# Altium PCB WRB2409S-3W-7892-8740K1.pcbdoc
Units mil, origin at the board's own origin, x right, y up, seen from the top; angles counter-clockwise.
Board outline 933.1 x 582.7 mil, 2 copper layers (Top Layer, Bottom Layer), stack 30.8 mil thick; 27 components, 17 nets, 72 pads, 29 vias.
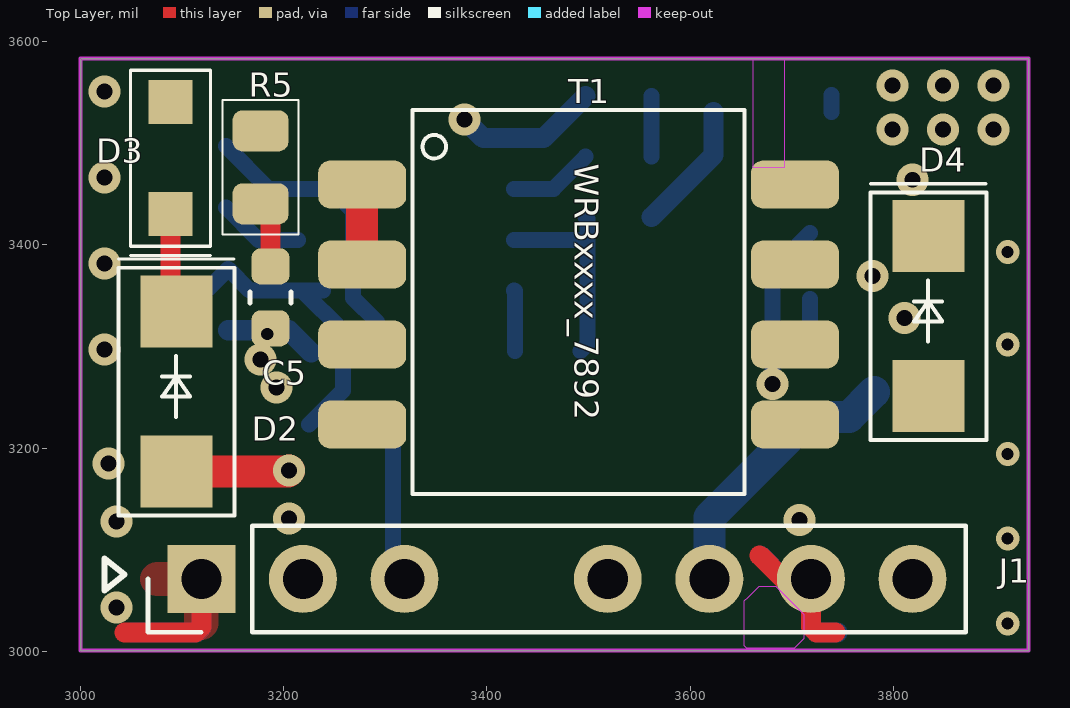
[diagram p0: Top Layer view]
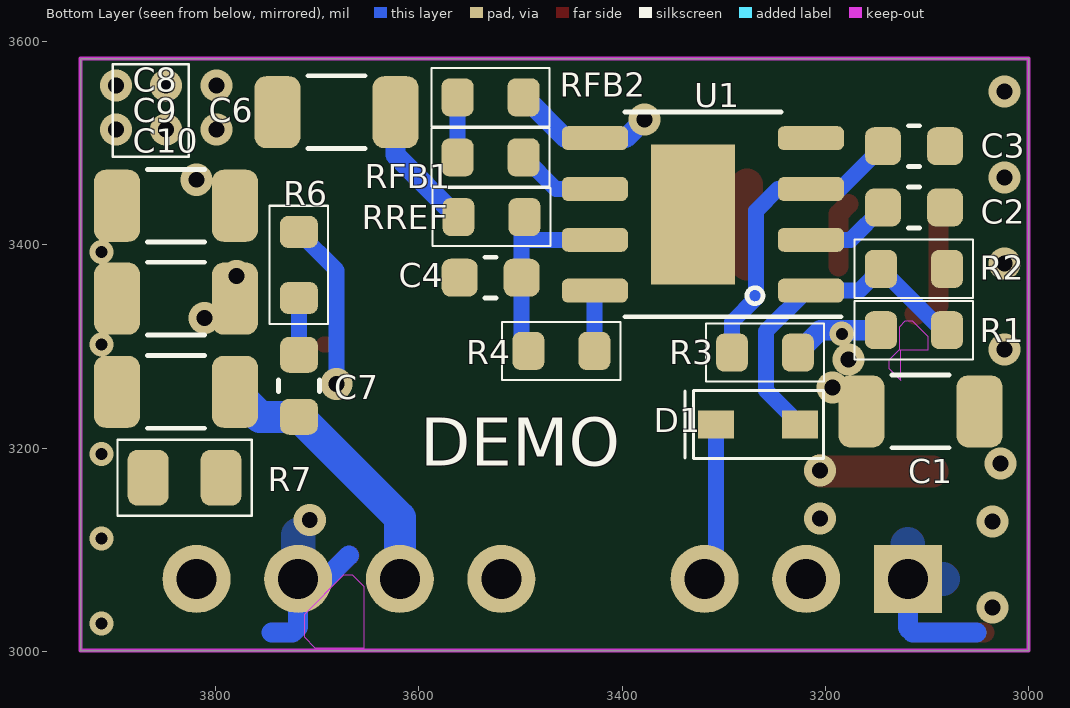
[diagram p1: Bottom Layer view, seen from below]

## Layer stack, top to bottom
Top Solder Mask Layer: solder mask 0.4, Dk 3.3
Top Layer: signal copper 1.4
Dielectric1: surface 28, FR4, Dk 4.5
Bottom Layer: signal copper 1.4
Bottom Solder Mask Layer: solder mask 0.4, Dk 3.3

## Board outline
3000,3583.5 3933.1,3583.5 3933.1,3000.8 3000,3000.8

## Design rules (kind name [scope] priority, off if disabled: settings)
BoardOutlineClearance safeClearance [All] p0: genericclearance=10 ignorepadtopadclearanceinfootprint=FALSE except(0: Arc-SplitContinuation Track-SplitContinuation SMDPad-SplitContinuation THPad-SplitContinuation Via-SplitContinuation Fill-SplitContinuation Poly-SplitContinuation Region-SplitContinuation Text-SplitContinuation)
BoardOutlineClearance Plane_innerPlane [All] p0: genericclearance=10 ignorepadtopadclearanceinfootprint=FALSE except(0: Arc-SplitContinuation Track-SplitContinuation SMDPad-SplitContinuation THPad-SplitContinuation Via-SplitContinuation Fill-SplitContinuation Poly-SplitContinuation Region-SplitContinuation Text-SplitContinuation)
BoardOutlineClearance Copper_CopperRegion [All] p0: genericclearance=10 ignorepadtopadclearanceinfootprint=FALSE except(0: Arc-SplitContinuation Track-SplitContinuation SMDPad-SplitContinuation THPad-SplitContinuation Via-SplitContinuation Fill-SplitContinuation Poly-SplitContinuation Region-SplitContinuation Text-SplitContinuation)
BoardOutlineClearance Copper_CopperRegion1 [All] p0: genericclearance=10 ignorepadtopadclearanceinfootprint=FALSE except(0: Arc-SplitContinuation Track-SplitContinuation SMDPad-SplitContinuation THPad-SplitContinuation Via-SplitContinuation Fill-SplitContinuation Poly-SplitContinuation Region-SplitContinuation Text-SplitContinuation)
BoardOutlineClearance Copper_CopperRegion2 [All] p0: genericclearance=10 ignorepadtopadclearanceinfootprint=FALSE except(0: Arc-SplitContinuation Track-SplitContinuation SMDPad-SplitContinuation THPad-SplitContinuation Via-SplitContinuation Fill-SplitContinuation Poly-SplitContinuation Region-SplitContinuation Text-SplitContinuation)
BoardOutlineClearance Copper_CopperRegion3 [All] p0: genericclearance=10 ignorepadtopadclearanceinfootprint=FALSE except(0: Arc-SplitContinuation Track-SplitContinuation SMDPad-SplitContinuation THPad-SplitContinuation Via-SplitContinuation Fill-SplitContinuation Poly-SplitContinuation Region-SplitContinuation Text-SplitContinuation)
BoardOutlineClearance Copper_CopperRegion4 [All] p0: genericclearance=10 ignorepadtopadclearanceinfootprint=FALSE except(0: Arc-SplitContinuation Track-SplitContinuation SMDPad-SplitContinuation THPad-SplitContinuation Via-SplitContinuation Fill-SplitContinuation Poly-SplitContinuation Region-SplitContinuation Text-SplitContinuation)
BoardOutlineClearance Copper_CopperRegion5 [All] p0: genericclearance=10 ignorepadtopadclearanceinfootprint=FALSE except(0: Arc-SplitContinuation Track-SplitContinuation SMDPad-SplitContinuation THPad-SplitContinuation Via-SplitContinuation Fill-SplitContinuation Poly-SplitContinuation Region-SplitContinuation Text-SplitContinuation)
BoardOutlineClearance Copper_CopperRegion6 [All] p0: genericclearance=10 ignorepadtopadclearanceinfootprint=FALSE except(0: Arc-SplitContinuation Track-SplitContinuation SMDPad-SplitContinuation THPad-SplitContinuation Via-SplitContinuation Fill-SplitContinuation Poly-SplitContinuation Region-SplitContinuation Text-SplitContinuation)
BoardOutlineClearance Copper_CopperRegion7 [All] p0: genericclearance=10 ignorepadtopadclearanceinfootprint=FALSE except(0: Arc-SplitContinuation Track-SplitContinuation SMDPad-SplitContinuation THPad-SplitContinuation Via-SplitContinuation Fill-SplitContinuation Poly-SplitContinuation Region-SplitContinuation Text-SplitContinuation)
BoardOutlineClearance Copper_CopperRegion8 [All] p0: genericclearance=10 ignorepadtopadclearanceinfootprint=FALSE except(0: Arc-SplitContinuation Track-SplitContinuation SMDPad-SplitContinuation THPad-SplitContinuation Via-SplitContinuation Fill-SplitContinuation Poly-SplitContinuation Region-SplitContinuation Text-SplitContinuation)
BoardOutlineClearance Copper_CopperRegion9 [All] p0: genericclearance=10 ignorepadtopadclearanceinfootprint=FALSE except(0: Arc-SplitContinuation Track-SplitContinuation SMDPad-SplitContinuation THPad-SplitContinuation Via-SplitContinuation Fill-SplitContinuation Poly-SplitContinuation Region-SplitContinuation Text-SplitContinuation)
BoardOutlineClearance Copper_CopperRegion10 [All] p0: genericclearance=10 ignorepadtopadclearanceinfootprint=FALSE except(0: Arc-SplitContinuation Track-SplitContinuation SMDPad-SplitContinuation THPad-SplitContinuation Via-SplitContinuation Fill-SplitContinuation Poly-SplitContinuation Region-SplitContinuation Text-SplitContinuation)
BoardOutlineClearance Copper_CopperRegion11 [All] p0: genericclearance=10 ignorepadtopadclearanceinfootprint=FALSE except(0: Arc-SplitContinuation Track-SplitContinuation SMDPad-SplitContinuation THPad-SplitContinuation Via-SplitContinuation Fill-SplitContinuation Poly-SplitContinuation Region-SplitContinuation Text-SplitContinuation)
BoardOutlineClearance Copper_CopperRegion12 [All] p0: genericclearance=10 ignorepadtopadclearanceinfootprint=FALSE except(0: Arc-SplitContinuation Track-SplitContinuation SMDPad-SplitContinuation THPad-SplitContinuation Via-SplitContinuation Fill-SplitContinuation Poly-SplitContinuation Region-SplitContinuation Text-SplitContinuation)
BoardOutlineClearance Copper_CopperRegion13 [All] p0: genericclearance=10 ignorepadtopadclearanceinfootprint=FALSE except(0: Arc-SplitContinuation Track-SplitContinuation SMDPad-SplitContinuation THPad-SplitContinuation Via-SplitContinuation Fill-SplitContinuation Poly-SplitContinuation Region-SplitContinuation Text-SplitContinuation)
BoardOutlineClearance Copper_CopperRegion14 [All] p0: genericclearance=10 ignorepadtopadclearanceinfootprint=FALSE except(0: Arc-SplitContinuation Track-SplitContinuation SMDPad-SplitContinuation THPad-SplitContinuation Via-SplitContinuation Fill-SplitContinuation Poly-SplitContinuation Region-SplitContinuation Text-SplitContinuation)
BoardOutlineClearance Copper_copperRegion1 [All] p0: genericclearance=10 ignorepadtopadclearanceinfootprint=FALSE except(0: Arc-SplitContinuation Track-SplitContinuation SMDPad-SplitContinuation THPad-SplitContinuation Via-SplitContinuation Fill-SplitContinuation Poly-SplitContinuation Region-SplitContinuation Text-SplitContinuation)
BoardOutlineClearance otherClearance [All] p0: genericclearance=10 ignorepadtopadclearanceinfootprint=FALSE except(0: Arc-SplitContinuation Track-SplitContinuation SMDPad-SplitContinuation THPad-SplitContinuation Via-SplitContinuation Fill-SplitContinuation Poly-SplitContinuation Region-SplitContinuation Text-SplitContinuation)
Clearance safeClearance [All] p1: gap=7 ignorepadtopadclearanceinfootprint=FALSE
Clearance Plane_innerPlane [All] p1: gap=7 ignorepadtopadclearanceinfootprint=FALSE
Clearance Copper_CopperRegion [All] p1: gap=7 ignorepadtopadclearanceinfootprint=FALSE
Clearance Copper_CopperRegion1 [All] p1: gap=7 ignorepadtopadclearanceinfootprint=FALSE
Clearance Copper_CopperRegion2 [All] p1: gap=7 ignorepadtopadclearanceinfootprint=FALSE
Clearance Copper_CopperRegion3 [All] p1: gap=7 ignorepadtopadclearanceinfootprint=FALSE
Clearance Copper_CopperRegion4 [All] p1: gap=7 ignorepadtopadclearanceinfootprint=FALSE
Clearance Copper_CopperRegion5 [All] p1: gap=7 ignorepadtopadclearanceinfootprint=FALSE
Clearance Copper_CopperRegion6 [All] p1: gap=7 ignorepadtopadclearanceinfootprint=FALSE
Clearance Copper_CopperRegion7 [All] p1: gap=7 ignorepadtopadclearanceinfootprint=FALSE
Clearance Copper_CopperRegion8 [All] p1: gap=7 ignorepadtopadclearanceinfootprint=FALSE
Clearance Copper_CopperRegion9 [All] p1: gap=7 ignorepadtopadclearanceinfootprint=FALSE
Clearance Copper_CopperRegion10 [All] p1: gap=7 ignorepadtopadclearanceinfootprint=FALSE
Clearance Copper_CopperRegion11 [All] p1: gap=7 ignorepadtopadclearanceinfootprint=FALSE
Clearance Copper_CopperRegion12 [All] p1: gap=7 ignorepadtopadclearanceinfootprint=FALSE
Clearance Copper_CopperRegion13 [All] p1: gap=7 ignorepadtopadclearanceinfootprint=FALSE
Clearance Copper_CopperRegion14 [All] p1: gap=7 ignorepadtopadclearanceinfootprint=FALSE
Clearance Copper_copperRegion1 [All] p1: gap=7 ignorepadtopadclearanceinfootprint=FALSE
Clearance otherClearance [All] p1: gap=7 ignorepadtopadclearanceinfootprint=FALSE
DiffPairsRouting differentialPair [All] p1: maxuncoupledlength=10 minlimit=6 maxlimit=Infinity mostfreqgap=6 toplayer_minwidth=5 toplayer_prefwidth=10 toplayer_maxwidth=100 bottomlayer_minwidth=5 bottomlayer_prefwidth=10 bottomlayer_maxwidth=100
PasteMaskExpansion Common [All] p1: expansion=0
PlaneConnect innerPlane [All] p1: planeconnectstyle=Relief reliefexpansion=20 reliefentries=4 reliefconductorwidth=10 reliefairgap=10
PolygonConnect CopperRegion [All] p1: connectstyle=Relief reliefentries=4 reliefconductorwidth=0 polygonreliefangle="90 Angle" airgapwidth=1
PolygonConnect CopperRegion1 [All] p1: connectstyle=Direct reliefentries=4 reliefconductorwidth=10 polygonreliefangle="90 Angle" airgapwidth=10
PolygonConnect CopperRegion2 [All] p1: connectstyle=Relief reliefentries=4 reliefconductorwidth=0 polygonreliefangle="90 Angle" airgapwidth=9.8425
PolygonConnect CopperRegion3 [All] p1: connectstyle=Relief reliefentries=4 reliefconductorwidth=0 polygonreliefangle="90 Angle" airgapwidth=1
PolygonConnect CopperRegion4 [All] p1: connectstyle=Relief reliefentries=4 reliefconductorwidth=0 polygonreliefangle="90 Angle" airgapwidth=1
PolygonConnect CopperRegion5 [All] p1: connectstyle=Relief reliefentries=4 reliefconductorwidth=0 polygonreliefangle="90 Angle" airgapwidth=1
PolygonConnect CopperRegion6 [All] p1: connectstyle=Relief reliefentries=4 reliefconductorwidth=0 polygonreliefangle="90 Angle" airgapwidth=1
PolygonConnect CopperRegion7 [All] p1: connectstyle=Relief reliefentries=4 reliefconductorwidth=0 polygonreliefangle="90 Angle" airgapwidth=1
PolygonConnect CopperRegion8 [All] p1: connectstyle=Relief reliefentries=4 reliefconductorwidth=0 polygonreliefangle="90 Angle" airgapwidth=1
PolygonConnect CopperRegion9 [All] p1: connectstyle=Relief reliefentries=4 reliefconductorwidth=0 polygonreliefangle="90 Angle" airgapwidth=1
PolygonConnect CopperRegion10 [All] p1: connectstyle=Relief reliefentries=4 reliefconductorwidth=0 polygonreliefangle="90 Angle" airgapwidth=1
PolygonConnect CopperRegion11 [All] p1: connectstyle=Relief reliefentries=4 reliefconductorwidth=0 polygonreliefangle="90 Angle" airgapwidth=1
PolygonConnect CopperRegion12 [All] p1: connectstyle=Relief reliefentries=4 reliefconductorwidth=0 polygonreliefangle="90 Angle" airgapwidth=1
PolygonConnect CopperRegion13 [All] p1: connectstyle=Relief reliefentries=4 reliefconductorwidth=0 polygonreliefangle="90 Angle" airgapwidth=1
PolygonConnect CopperRegion14 [All] p1: connectstyle=Relief reliefentries=4 reliefconductorwidth=0 polygonreliefangle="90 Angle" airgapwidth=1
PolygonConnect copperRegion1 [All] p1: connectstyle=Relief reliefentries=4 reliefconductorwidth=10 polygonreliefangle="90 Angle" airgapwidth=10
RoutingVias viaSize [All] p1: viastyle="Through Hole" holewidth=12.0078 minholewidth=11.811 maxholewidth=236.2204 width=12.0078 minwidth=11.811 maxwidth=236.2204
SolderMaskExpansion Common [All] p1: useseparateexpansions=TRUE expansion=0 expansionbottom=0
Width trackWidth [All] p1: maxlimit=100 minlimit=5 preferedwidth=10

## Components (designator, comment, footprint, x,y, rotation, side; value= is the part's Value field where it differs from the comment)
C1 "10uF" C1206#1 3106.3,3236.2 r180 bottom
C2 "1uF" C0603 3112.8,3436.9 r0 bottom
C3 "1uF" C0603 3112.8,3497.2 r180 bottom
C4 "10pF" C0603 3529.5,3367.8 r180 bottom
C5 "470pF" C0603 3187,3348.4 r270 top
C6 "1nF" C1206#1 3681.1,3530.7 r180 bottom
C7 "C" coileasy:C_0603 3718.1,3261.4 r270 bottom
C8 "22uF" C1206#2 3839.2,3438.6 r0 bottom
C9 "22uF" C1206#2 3839.2,3347.2 r0 bottom
C10 "22uF" C1206#2 3839.2,3255.5 r0 bottom
D1 "B0540WS" SOD-323_L1.8-W1.3-LS2.5-RD 3266.1,3223.6 r180 bottom
D2 "1SMA5930A" SMA_L4.3-W2.6-LS5.2-RD 3094.5,3255.9 r270 top
D3 "DSS210" SOD-123_L2.8-W1.8-LS3.7-FD 3090.6,3489.4 r90 top
D4 "SS38" SMA_L4.4-W2.8-LS5.4-RD 3834.6,3329.9 r270 top
J1 "Coileasy_Conn_01x07_1" coileasy:PinHeader_01x07_1_P2.54mm_Vertical 3118.9,3071.3 r90 top
R1 "910kΩ" R0603#1 3112.8,3316.1 r0 bottom
R2 "100kΩ" R0603#1 3112.8,3376.5 r0 bottom
R3 "0Ω" R0603#2 3259.4,3294.1 r180 bottom
R4 "R" coileasy:R_0603#1 3459.8,3295.7 r0 bottom
R5 "2.2kΩ" R0805#1 3177.2,3476.4 r90 top
R6 "R" coileasy:R_0603#2 3718.1,3380.3 r90 bottom
R7 "1.5kΩ" R0805#2 3830.7,3170.9 r0 bottom
RFB1 "91kΩ" R0603#1 3529.5,3486.2 r180 bottom
RFB2 "3.9kΩ" R0603#1 3529.5,3545.3 r0 bottom
RREF "10kΩ" R0603#3 3528.7,3427.5 r180 bottom
T1 "CMB8740K1" "coileasy:SMD-8P, 11.55x9.6, ER9.5 4+4" 3490.3,3343.7 r0 top
U1 "CMP7892" ESOP-8_L4.9-W3.9-P1.27-LS6.0-BL-EP3.3 3320.5,3430.1 r0 bottom

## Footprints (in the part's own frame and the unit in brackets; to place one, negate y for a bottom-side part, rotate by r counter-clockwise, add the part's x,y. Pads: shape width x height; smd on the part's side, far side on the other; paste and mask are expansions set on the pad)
C0603 [mil]
  rrect50% 35.4x37.4 smd paste+0 mask+0: 1(-30.5,0) 2(30.5,0)
  silkscreen extent -6,-20 6,20
C1206#1 [mil]
  rrect50% 45.3x70.9 smd paste+0 mask+0: 1(-58.1,0) 2(58.1,0)
  silkscreen extent -28,-36 28,36
C1206#2 [mil]
  rrect50% 45.3x70.9 smd paste+0 mask+0: 1(-58.1,0) 2(58,0)
  silkscreen extent -28,-36 28,36
coileasy:C_0603 [mil]
  rrect50% 35.4x37.4 smd paste+0 mask+0: 1(-30.5,0) 2(30.5,0)
  silkscreen extent -6,-20 6,20
coileasy:PinHeader_01x07_1_P2.54mm_Vertical [mil]
  rect 66.9x66.9 hole 39.4 paste+0 mask+0: 1(0,0)
  round 66.9 hole 39.4 paste+0 mask+0: 2(0,-100) 3(0,-200) 5(0,-400) 6(0,-500) 7(0,-600) 8(0,-700)
  silkscreen extent -52,-752 52,52
coileasy:R_0603#1 [mil]
  rrect50% 31.5x37.4 smd paste+0 mask+0: 1(-32.4,0) 2(32.5,0)
  silkscreen extent -58,-29 58,29
coileasy:R_0603#2 [mil]
  rrect50% 31.5x37.4 smd paste+0 mask+0: 1(-32.5,0) 2(32.5,0)
  silkscreen extent -58,-29 58,29
"coileasy:SMD-8P, 11.55x9.6, ER9.5 4+4" [mil]
  rrect50% 86.6x47.2 smd paste+0 mask+0: 1(-213.1,115.7) 2(-213.1,37) 3(-213.1,-41.7) 4(-213.1,-120.5) 5(213,-120.5) 6(213,-41.7) 7(213,37) 8(213,115.7)
  silkscreen extent -163,-189 163,189
ESOP-8_L4.9-W3.9-P1.27-LS6.0-BL-EP3.3 [mil]
  rrect50% 65x23.6 smd paste+0 mask+0: 1(-106.3,75) 2(-106.3,25) 3(-106.3,-25) 4(-106.3,-75) 5(106.3,-75) 6(106.3,-25) 7(106.3,25) 8(106.3,75)
  rect 82.7x137.8 smd paste+0 mask+0: 9(9.8,0)
  silkscreen extent -136,-101 77,101
R0603#1 [mil]
  rrect50% 31.5x37.4 smd paste+0 mask+0: 1(-32.5,0) 2(32.5,0)
  silkscreen extent -58,-29 58,29
R0603#2 [mil]
  rrect50% 31.5x37.4 smd paste+0 mask+0: 1(-32.5,0) 2(32.4,0)
  silkscreen extent -58,-29 58,29
R0603#3 [mil]
  rrect50% 31.5x37.4 smd paste+0 mask+0: 1(-32.4,0) 2(32.5,0)
  silkscreen extent -58,-29 58,29
R0805#1 [mil]
  rrect48% 40.4x55.1 smd paste+0 mask+0: 1(-35.9,0) 2(35.9,0)
  silkscreen extent -66,-37 66,37
R0805#2 [mil]
  rrect50% 40.4x55.1 smd paste+0 mask+0: 1(-35.9,0) 2(35.9,0)
  silkscreen extent -66,-37 66,37
SMA_L4.3-W2.6-LS5.2-RD [mil]
  rect 70.9x70.9 smd paste+0 mask+0: 1(-78.7,0) 2(78.7,0)
  silkscreen extent -130,-57 122,57
SMA_L4.4-W2.8-LS5.4-RD [mil]
  rect 70.9x70.9 smd paste+0 mask+0: 1(-78.8,0) 2(78.7,0)
  silkscreen extent -130,-57 122,57
SOD-123_L2.8-W1.8-LS3.7-FD [mil]
  rect 43.3x43.3 smd paste+0 mask+0: 1(-59.1,2) 2(51.2,2)
  silkscreen extent -100,-37 83,41
SOD-323_L1.8-W1.3-LS2.5-RD [mil]
  rect 35.4x27.6 smd paste+0 mask+0: 1(-41.4,-0.4) 2(41.3,-0.4)
  silkscreen extent -72,-34 64,33

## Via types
v1: diameter 31.5, hole 15.7, Top Layer to Bottom Layer, 23 vias
v2: diameter 23.6, hole 11.8, Top Layer to Bottom Layer, 5 vias
v3: diameter 24, hole 12, Top Layer to Bottom Layer, 1 vias

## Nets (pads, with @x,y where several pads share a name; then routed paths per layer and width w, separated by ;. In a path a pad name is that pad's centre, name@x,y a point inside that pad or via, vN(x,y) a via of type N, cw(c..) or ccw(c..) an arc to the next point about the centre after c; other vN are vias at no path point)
$1N2: D4.2 R6.2 T1.5 T1.6 | length 175.9
  Top Layer w15.7: T1.6@3681.9,3302 T1.6@3693.5,3302
  Bottom Layer w15.7: v1(3681.1,3263) 3681.1,3375 R6.2@3718.1,3412
$1N4: C5.1 R5.1 | length 65.6
  Top Layer w19.7: R5.1 3187,3430.6 C5.1
$1N11: C2.2 U1.2 | length 84.1
  Bottom Layer w15.7: C2.2 3175.1,3405.1 U1.2
$1N13: C3.1 R3.1 U1.3 | length 300.6
  Bottom Layer w15.7: C3.1 3185.4,3455.1 U1.3 3246.7,3455.1 3268.1,3433.7 3268.1,3348 3291.9,3324.2 R3.1
$1N26: RFB1.1 RFB2.2 | length 59.6
  Bottom Layer w15.7: RFB1.1@3562,3486.9 RFB2.2@3562,3546.5
$1N479: C7.1 R6.1 | length 55.1
  Bottom Layer w15.7: C7.1 R6.1@3718.1,3347
$1N482: D2.1 D3.1 | length 99.8
  Top Layer w19.7: D3.1 3088.6,3340.6 D2.1 ; D2.1@3111,3331.1 D2.1@3112.2,3332.3
$1N487: R4.1 U1.8 | length 59.6
  Bottom Layer w15.7: U1.8 3427.4,3354.5 R4.1
CTRL: D1.1 J1.3 | length 157.8
  Bottom Layer w15.7: D1.1 3307.5,3081.5 J1.3@3318.9,3070.1
EN: D1.2 R1.1 R2.2 U1.1 | length 354.7
  Bottom Layer w15.7: R1.1 3084.9,3316.1 R2.2 3166.7,3355.1 U1.1 U1.1@3218.3,3355.1 ; D1.2 3258.5,3256.9 3258.5,3314.9 U1.1@3218.3,3355.1 ; U1.1@3238.6,3355.1 U1.1@3218.3,3355.1
GND1: C1.2 C2.1 C3.2 C4.1 C6.2 J1.1 R2.1 RREF.1 U1.4 U1.9 | length 368.8
  Top Layer w19.7: 3043.3,3018.5 3113,3018.5 3118.9,3024.4 J1.1@3118.9,3070.1
  Bottom Layer w19.7: 3051.2,3018.5 3114.2,3018.5 3118.9,3023.3 J1.1@3118.9,3070.1 ; RREF.1@3562,3427.4 3623,3488.4 C6.2
  other v1: 3035.4,3043.3 3035.4,3128 3027.6,3185 3023.6,3297.2 3023.6,3381.9 3023.6,3466.5 3023.6,3551.2
GND2: C6.1 C8.2 C9.2 C10.2 J1.7 R7.2 T1.7 T1.8 | length 286
  Top Layer w19.7: 3668.5,3094.5 3691.7,3071.3 J1.7 3718.9,3023.9 3724.3,3018.5 3742.9,3018.5
  Bottom Layer w15.7: C6.1 C6.1@3739.2,3547.8
  Bottom Layer w19.7: 3668.9,3094.5 3692.1,3071.3 J1.7 3718.9,3023.9 3724.3,3018.5 3744.9,3018.5
  other v1: 3707.5,3129.1 3799.2,3513.8 3848.8,3513.8 3898.4,3513.8 3799.2,3557.1 3848.8,3557.1 3898.4,3557.1
  other v2: 3912.6,3027.6 3912.6,3111 3912.6,3194.5 3912.6,3302 3912.6,3393.3
RFB: RFB1.2 U1.6 | length 83.4
  Bottom Layer w15.7: U1.6 3465.3,3455.1 RFB1.2@3497,3486.9
RREF: C4.2 R4.2 RREF.2 U1.7 | length 207.7
  Bottom Layer w15.7: U1.7 3498.6,3405.1 3499,3404.7 ; R4.2 3499,3302.4 C4.2 3499,3404.7 ; RREF.2@3497,3427.4 3499,3425.4 3499,3404.7
SW: D3.2 R5.2 RFB2.1 T1.1 T1.2 U1.5 | length 222.5
  Top Layer w31.5: T1.2 T1.1
  Bottom Layer w19.7: v1(3378,3523.6) 3396.5,3505.1 U1.5 3455.7,3505.1 RFB2.1@3497,3546.5
VIN: C1.1 C5.2 D2.2 J1.2 R1.2 R3.2 T1.3 T1.4 | length 206.9
  Top Layer w31.5: D2.2 3204.3,3177.2 v1(3205.1,3178)
  Bottom Layer w20: R1.2 v3@3180,3316.1 ; v3(3183.7,3312.5) v3@3180,3316.1 ; R3.2 3204.9,3316.1 v3@3180,3316.1
  other v1: 3205.1,3130.7 3192.9,3259.8 3177.2,3287.4
VOUT: C7.2 C8.1 C9.1 C10.1 D4.1 J1.6 R7.1 | length 276.3
  Bottom Layer w31.5: J1.6@3618.9,3068.9 3618.9,3131.7 C7.2 3756.5,3230.9 C10.1
  other v1: 3811,3328 3779.5,3369.3 3818.9,3464.2
pads on no net: J1.5 J1.8

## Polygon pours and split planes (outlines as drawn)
GND2 on Bottom Layer (solid, remove dead copper, pour order 16): 3933.1,3149.6 3933.1,3000 3657.5,3000 3653.9,3003.5 3653.9,3119.3 3684.3,3149.6 3925.2,3149.6
GND1 on Top Layer (solid, remove dead copper, pour order 0): 3000,3105 3000,3582.7 3051.7,3582.7 3051.2,3385.8 3051.2,3127 3153.5,3127 3153.5,3103.1
GND1 on Top Layer (solid, remove dead copper, pour order 2): 3000,3118.1 3153.5,3118.1 3153.5,3000 3000,3000
GND1 on Bottom Layer (solid, remove dead copper, pour order 18): 3000,3161.4 3153.5,3161.4 3153.5,3000 3000,3000
GND2 on Top Layer (solid, remove dead copper, pour order 4): 3748,3358.3 3748,3474 3771.7,3474 3771.7,3574.8 3661.4,3574.8 3661.4,3358.3
GND2 on Bottom Layer (solid, remove dead copper, pour order 20): 3716.5,3582.7 3933.1,3582.7 3933.1,3141.7 3933.1,3137.8 3854.3,3137.8 3854.3,3488.2 3716.5,3488.2
VOUT on Bottom Layer (solid, remove dead copper, pour order 22): 3828.7,3143.7 3828.7,3481.9 3753.1,3481.9 3753.1,3143.7
VOUT on Top Layer (solid, remove dead copper, pour order 6): 3753.9,3300.4 3753.9,3482.7 3889.8,3482.7 3889.8,3300.4
$1N2 on Top Layer (solid, remove dead copper, pour order 8): 3657.5,3205.9 3657.5,3292.5 3889.8,3292.5 3889.8,3205.9
SW on Top Layer (solid, remove dead copper, pour order 10): 3066.9,3561.2 3399.6,3561.2 3399.6,3489.4 3317.9,3489.4 3317.9,3434.3 3252,3434.3 3252,3491.3 3066.9,3491.3
GND1 on Bottom Layer (solid, remove dead copper, pour order 24): 3371.7,3405.5 3371.7,3263 3372,3263 3445.3,3263 3519.3,3263 3539.4,3283.5 3539.4,3448.8 3578.7,3448.8 3578.7,3248 3559.1,3228.3 3334.6,3228.3 3330.7,3232.3 3330.7,3311 3318.9,3322.8 3315,3322.8 3289,3348.8 3289,3405.5
GND2 on Top Layer (solid, remove dead copper, pour order 12): 3661.4,3367.3 3661.4,3581.9 3933.1,3581.9 3933.1,3000 3657.5,3000
GND1 on Bottom Layer (solid, remove dead copper, pour order 26): 3153.5,3149.6 3153.5,3492.1 3244.1,3492.1 3271.7,3464.6 3354.3,3464.6 3358.3,3468.5 3358.3,3582.7 3000,3582.7 3000,3149.6
VIN on Bottom Layer (solid, remove dead copper, pour order 28): 3165.4,3003.9 3165.4,3208.7 3129.9,3208.7 3129.9,3330.7 3133.9,3334.6 3236.2,3334.6 3252,3318.9 3252,3000 3169.3,3000
VIN on Top Layer (solid, remove dead copper, pour order 14): 3252,3000 3252,3189 3322.8,3189 3322.8,3326.8 3165.4,3326.8 3165.4,3000 3169.3,3000

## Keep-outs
Top Layer:
  region: 3661.4,3476.4 3692.9,3476.4 3692.9,3582.7 3661.4,3582.7
  region: 3684.3,3064.2 3711.8,3036.6 3711.8,3012.6 3702.4,3003.1 3655.5,3003.1 3653.1,3005.5 3653.1,3049.6 3657.1,3053.5 3657.1,3053.1 3668.1,3064.2
Bottom Layer:
  region: 3099.2,3296.5 3126.8,3296.5 3126.8,3319.7 3121.3,3325.2 3114.4,3325.2 3099.2,3310
  region: 3125.6,3266.9 3125.6,3296.5 3127.6,3296.5 3137.4,3286.6 3137.4,3278.7
  region: 3674.3,3075 3713,3036.2 3713,3014.2 3702.4,3003.5 3653.9,3003.5 3653.9,3063.8 3665.1,3075
Board Outline Layer:
  the board outline again, w3.9

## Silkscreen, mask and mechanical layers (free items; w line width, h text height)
Top Silkscreen Layer:
  lines w5.9: 3023.6,3060 3023.6,3091.5 3043.3,3075.8 3023.6,3060
  text "WRBxxxx_7892" at 3486.6,3479.9 h23.6 r270
Bottom Silkscreen Layer:
  lines w2.4: 3826.8,3487 3901.2,3487 3901.2,3578 3826.8,3578 3826.8,3487
  text "DEMO" at 3598.8,3182.6 h47.2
